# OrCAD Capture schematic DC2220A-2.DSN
size Custom
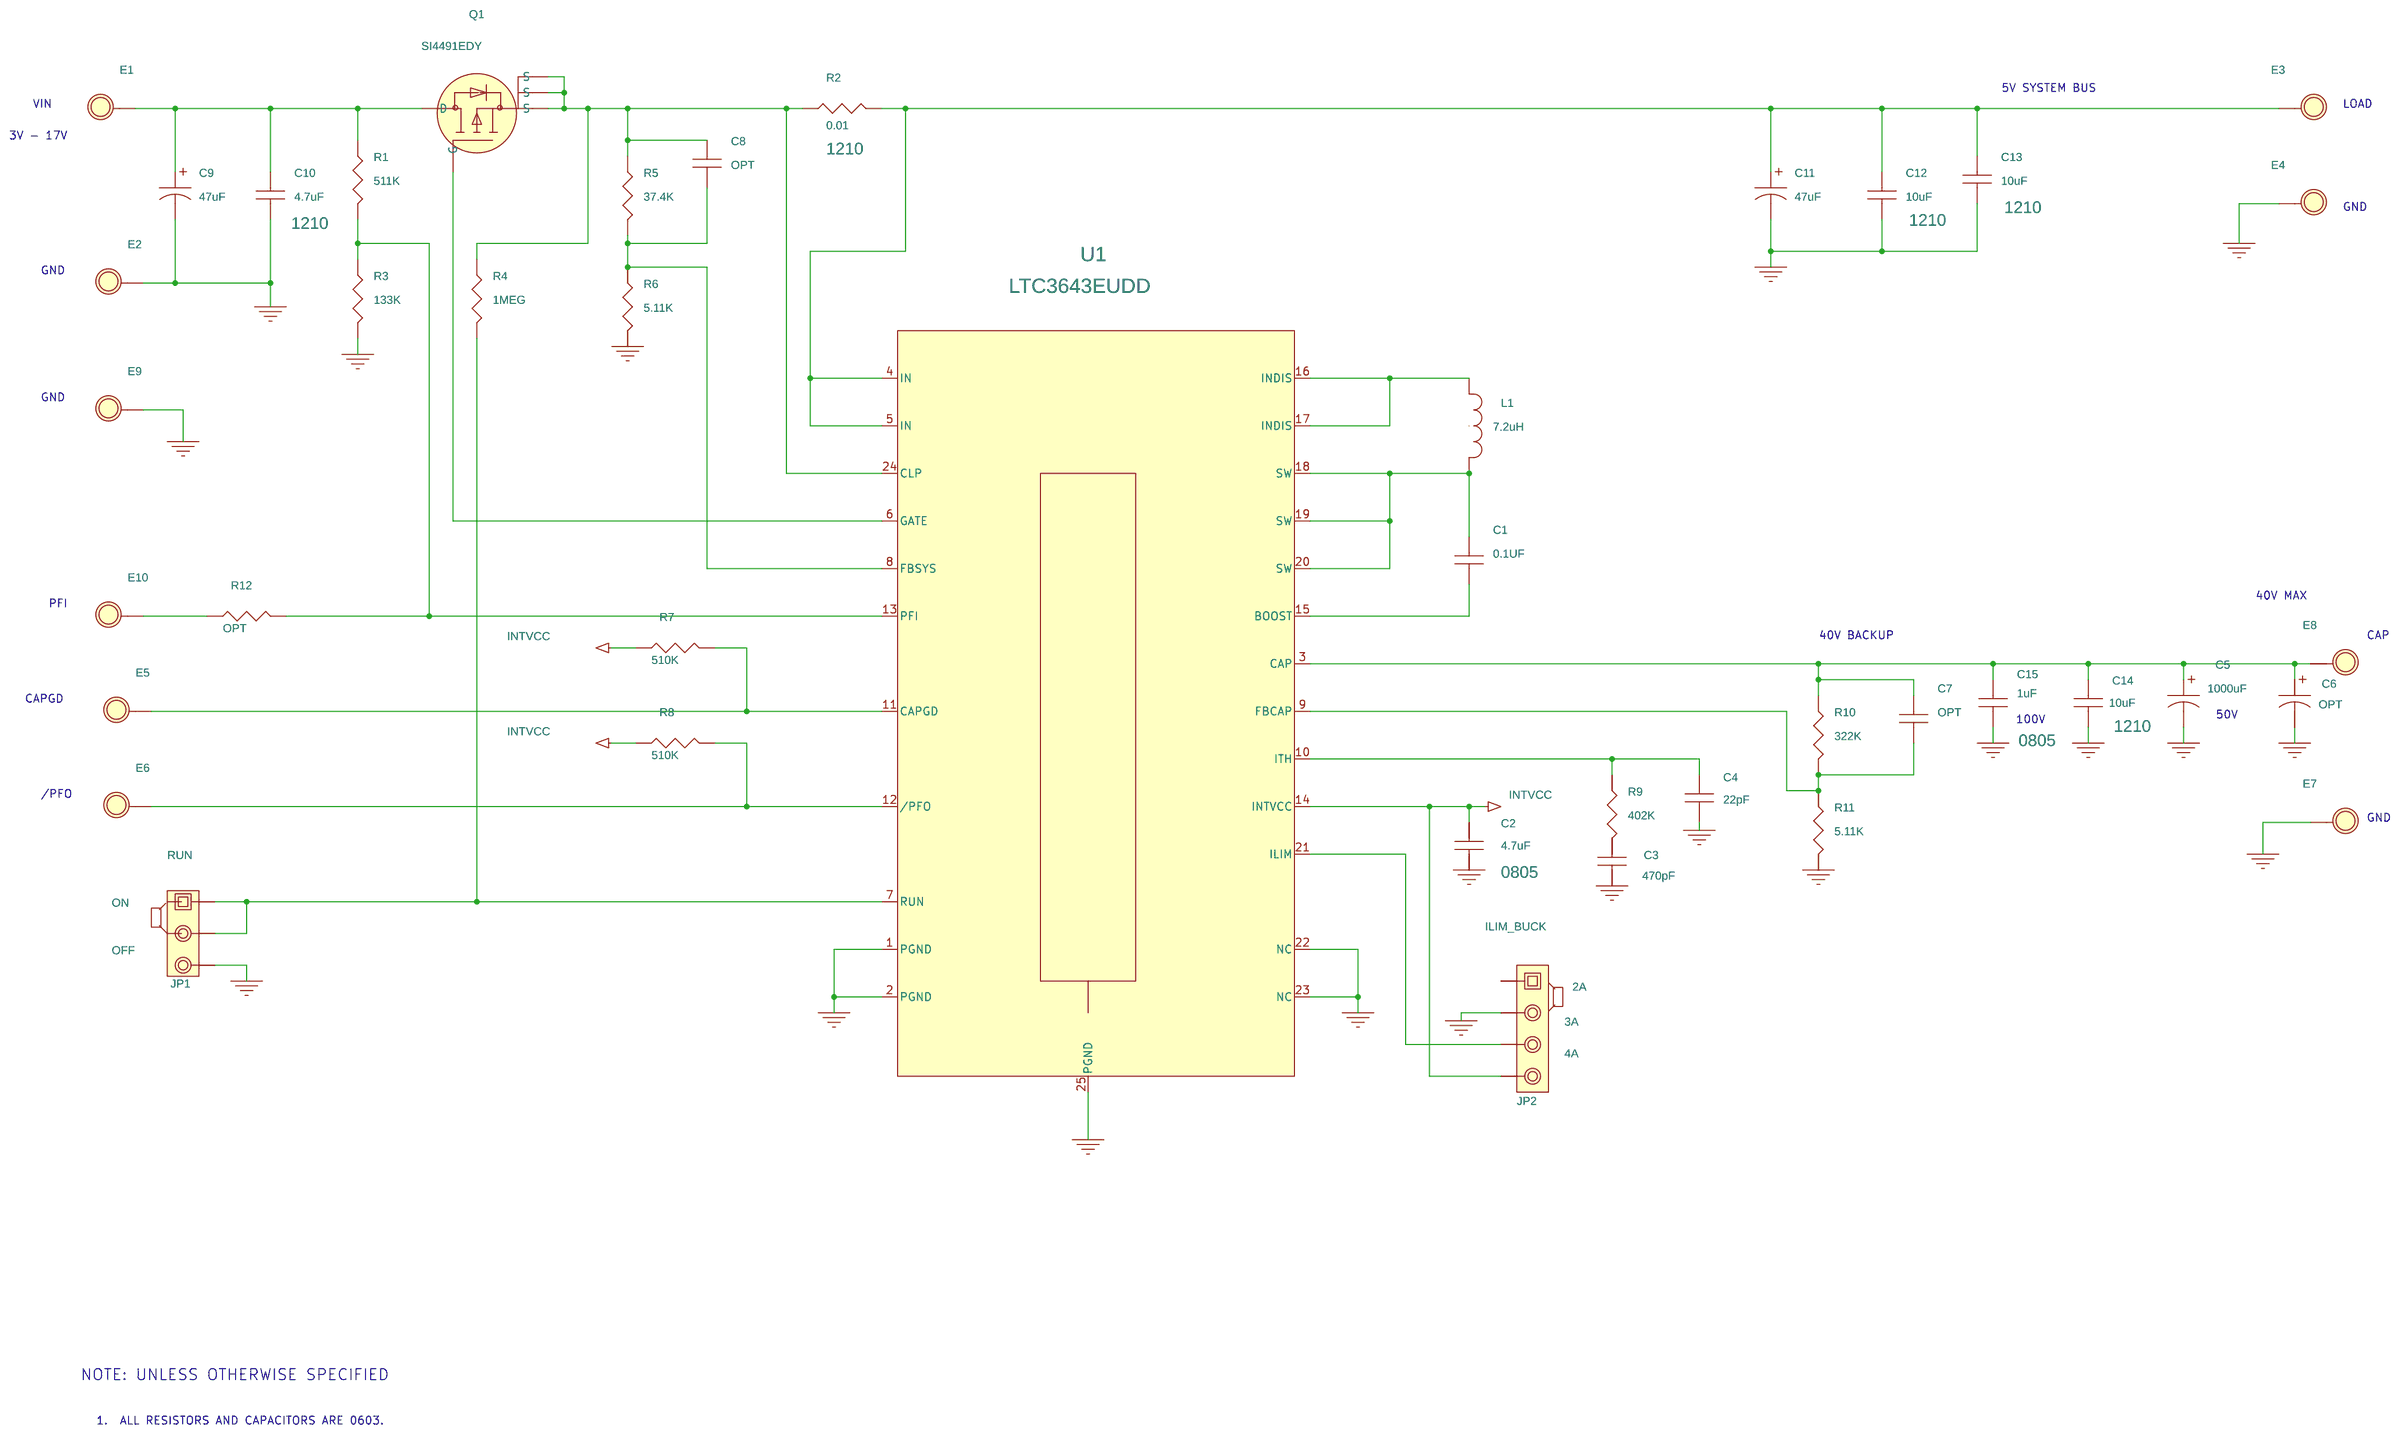
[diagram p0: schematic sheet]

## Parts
C1  0.1UF  [0603]
C2  4.7uF  [0805]
C3  470pF  [0603]
C4  22pF  [0603]
C5  1000uF  [C-EEVFK-16X16.5]
C6  OPT  [C-EEVFK-16X16.5]
C7  OPT  [0603]
C8  OPT  [0603]
C9  47uF  [C-TQC-D2SIZE]
C10  4.7uF  [1210]
C11  47uF  [C-TQC-D2SIZE]
C12  10uF  [1210]
C13  10uF  [1210]
C14  10uF  [1210]
C15  1uF  [0805]
E1  Testpoint  [MM/2501]
E2  Testpoint  [MM/2501]
E3  Testpoint  [MM/2501]
E4  Testpoint  [MM/2501]
E5  Testpoint  [MM/2501]
E6  Testpoint  [MM/2501]
E7  Testpoint  [MM/2501]
E8  Testpoint  [MM/2501]
E9  Testpoint  [MM/2501]
E10  Testpoint  [MM/2501]
JP1  3 Pins 2mm Ctrs.  [HD1X3-079]
JP2  4 Pins 2mm Ctrs.  [HD1X4-079]
L1  7.2uH  [IND-CDEP105]
Q1  SI4491EDY  [LFPAK]
R1  511K  [0603]
R2  0.01  [1210]
R3  133K  [0603]
R4  1MEG  [0603]
R5  37.4K  [0603]
R6  5.11K  [0603]
R7  510K  [0603]
R8  510K  [0603]
R9  402K  [0603]
R10  322K  [0603]
R11  5.11K  [0603]
R12  OPT  [0603]
U1  LTC3643EUDD  [QFN24UDD-3X5]
XJP3  2mm Ctrs.
XJP4  2mm Ctrs.

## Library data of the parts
C1-C4 C7 C8 C10 C12-C15 = CAP_NP: Voltage: 10V
C5 C6 C9 C11 = CAP_13: CAP, 7343 330uF 20% 2.5V POSCAP; COMPFIXED: 2.5V; Part Number: SANYO 2R5TPE330M9; Voltage: 2.5V
E1 E2 E4-E10 = MillMax-2501-2_4: V: GND
E3 = MillMax-2501-2_3: V: GND
JP1 = Samtec_TMM-103-02-L-S: 10th Part Field: RUN; 11th Part Field: OFF; 12th Part Field: RUN1; 9th Part Field: ON
JP2 = HD1X4: 10th Part Field: 3A; 11th Part Field: 4A; 12th Part Field: ILIM_BUCK; 9th Part Field: 2A
L1 = IND-PQA2050-3P_0
Q1 = MOS_FET_1: XSTR, N-CHANNEL DMOS FET; Part Number: ZETEX 2N7002TA
R1-R12 = AAC-0603
U1 = LTC3643IUDD-QFN24-3X5_2
XJP3 XJP4 = Samtec_2SN-BK-G

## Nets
GND: C2.2 C3.2 C4.2 C5.2 C6.2 C9.2 C10.2 C11.2 C12.2 C13.2 C14.2 C15.2 E2.1 E4.1 E7.1 E9.1 JP1.3 JP2.2 R3.2 R6.2 R11.2 U1.1(PGND) U1.2(PGND) U1.22(NC) U1.23(NC) U1.25(PGND)
INTVCC: C2.1 JP2.4 R7.1 R8.1 U1.14(INTVCC)
N17682929: R1.2 R3.1 R12.2 U1.13(PFI)
N17683208: C11.1 C12.1 C13.1 E3.1 R2.2 U1.4(IN) U1.5(IN)
N17683303: C8.1 Q1.1(S) Q1.2(S) Q1.3(S) R2.1 R4.1 R5.1 U1.24(CLP)
N17683394: C8.2 R5.2 R6.1 U1.8(FBSYS)
N17683465: Q1.4(G) U1.6(GATE)
N17683967: C9.1 C10.1 E1.1 Q1.5(D) R1.1
N17684750: JP1.1 JP1.2 R4.2 U1.7(RUN)
N17685621: E5.1 R7.2 U1.11(CAPGD)
N17685726: E6.1 R8.2 U1.12(/PFO)
N17688596: L1.2 U1.16(INDIS) U1.17(INDIS)
N17688754: C1.1 L1.1 U1.18(SW) U1.19(SW) U1.20(SW)
N17689333: C1.2 U1.15(BOOST)
N17691487: JP2.3 U1.21(ILIM)
N17695175: C4.1 R9.1 U1.10(ITH)
N17696541: C5.1 C6.1 C7.1 C14.1 C15.1 E8.1 R10.1 U1.3(CAP)
N17696993: C7.2 R10.2 R11.1 U1.9(FBCAP)
N17737895: C3.1 R9.2
N17787557: E10.1 R12.1

Not connected (* = marked no-connect by the designer): JP2 1; L1 3

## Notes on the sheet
- 5V SYSTEM BUS
- VIN
- LOAD
- 3V - 17V
- GND
- GND
- GND
- 40V MAX
- PFI
- 40V BACKUP
- CAP
- CAPGD
- 100V
- 50V
- /PFO
- GND
- NOTE: UNLESS OTHERWISE SPECIFIED
- 1.  ALL RESISTORS AND CAPACITORS ARE 0603.
